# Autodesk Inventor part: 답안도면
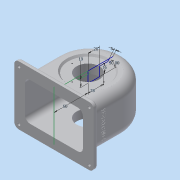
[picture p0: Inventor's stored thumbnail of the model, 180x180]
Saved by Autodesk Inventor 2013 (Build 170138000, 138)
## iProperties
Created: 2016-01
Part Number: 답안도면
Material: 일반
Document SubType Name: Modeling
Designer: Administrator
Density: 1 g/cm^3
Author: Administrator
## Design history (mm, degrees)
sketch "스케치1"
  geometry: L1 (-51, 0)-(-51, -64); L2 (51, 0)-(51, -64); L3 (-57, -64)-(-57, 0); L4 (57, 0)-(57, -64); L5 (-57, -64)-(-51, -64); L6 (51, -64)-(57, -64); A1 r 51 centre (0, 0) between (51, 0) and (-51, 0); A2 r 57 centre (0, 0) between (57, 0) and (-57, 0); 1 further point
  constraints: 12 end point, 4 point on circle, 2 centre point, 2 parallel, 2 perpendicular, 2 tangent, 1 coincident, 1 collinear, 1 vertical
  dimensions: "d0" = 102 diameter of A1; "d2" = 6 distance between parallel lines of L3 L1; "d4" = 6 radial gap between concentric circles of A1 A2; "d6" = 64 vertical distance of L4.end point (0, 0); "d7" = 6 distance between parallel lines of L2 L4
extrude "돌출1" new body sketch "스케치1" stored distance "d8" = 77; taper "d9" = 0 deg
sketch "스케치2"
  geometry: L1 (-51, -64)-(-51, 0) reference; L2 (51, 0)-(51, -64) reference; L3 (-51, -64)-(-46.848, -64); L4 (-46.848, -64)-(51, -64); A1 r 51 centre (0, 0) between (51, 0) and (-51, 0) reference; 1 further point
  constraints: 4 end point, 1 collinear
extrude "돌출2" join sketch "스케치2" distance "d10" = 5; taper "d11" = 0 deg
sketch "스케치3"
  geometry: L1 (51, 0)-(51, -64) reference; L2 (51, -64)-(57, -64) reference; L3 (57, -64)-(57, 0) reference; L4 (-57, 0)-(-57, -64) reference; L5 (-57, -64)-(-51, -64) reference; L6 (-51, -64)-(-51, 0) reference; L7 (-51, -64)-(51, -64); A1 r 51 centre (0, 0) between (51, 0) and (-51, 0) reference; A2 r 57 centre (0, 0) between (57, 0) and (-57, 0) reference; 1 further point
  constraints: 2 end point, 1 perpendicular
extrude "돌출3" join sketch "스케치3" distance "d12" = 5; taper "d13" = 0 deg
sketch "스케치5"
  geometry: L1 (-57, -64)-(57, -64) reference; C1 r 31 at (0, -4); A1 r 57 centre (0, 0) between (57, 0) and (-57, 0) reference; 1 further point
  constraints: 1 centre point, 1 vertical alignment
  dimensions: "d89" = 62 diameter of C1; "d91" = 60 distance from line of L1 C1.centre
extrude "돌출4" join sketch "스케치5" distance "d25" = 10; taper "d26" = 0 deg
sketch "스케치6"
  geometry: L1 (127, 90.5)-(-13, 90.5); L2 (-13, 90.5)-(-13, -13.5); L3 (-13, -13.5)-(127, -13.5); L4 (127, -13.5)-(127, 90.5); L5 (0, 77)-(114, 77) reference; L6 (114, 0)-(114, 77) reference; L7 (114, 0)-(0, 0) reference; L8 (0, 0)-(0, 77) reference; 1 further point
  constraints: 8 end point, 2 parallel, 1 horizontal, 1 perpendicular
  dimensions: "d27" = 140 distance of L2.end L3.end; "d29" = 104 distance of L3.end L1.start; "d30" = 70 distance from line of point (57, 38.5) L4; "d31" = 52 distance from line of L1 point (57, 38.5)
fillet "모깎기1" dims "d34" = 9
extrude "돌출7" join sketch "스케치6" distance "d48" = 7; taper "d49" = 0 deg
fillet "모깎기4" dims "d50" = 17
fillet "모깎기5" dims "d73" = 8
fillet "모깎기6" dims "d74" = 3
sketch "스케치11"
  geometry: L1 (124, 104)-(0, 104) reference; L2 (-8, 96)-(-8, 8) reference; L3 (0, 0)-(124, 0) reference; L4 (132, 8)-(132, 96) reference; C1 r 2.5 at (0, 96); C2 r 2.5 at (0, 8); C3 r 2.5 at (124, 8); C4 r 2.5 at (124, 96); A1 r 8 centre (0, 96) between (0, 104) and (-8, 96) reference; A2 r 8 centre (0, 8) between (-8, 8) and (0, 0) reference; A3 r 8 centre (124, 8) between (124, 0) and (132, 8) reference; A4 r 8 centre (124, 96) between (132, 96) and (124, 104) reference; 1 further point
  constraints: 4 centre point, 4 coincident
  dimensions: "d75" = 5 diameter of C1; "d77" = 5 diameter of C4; "d78" = 5 diameter of C3; "d79" = 5 diameter of C2
sketch "스케치12"
  geometry: L1 (-57, 38.5)-(0, 38.5) reference; L2 (0, 33.5)-(-64, 33.5) reference; L3 (-64, -44)-(-64, 44) reference; L4 (-4, 38.5)-(-4, 19.5); L5 (-4, 19.5)-(24, 19.5); L6 (24, 19.5)-(39.943, 38.5); L7 (0, 38.5)-(40, 38.5) reference; L8 (16, 19.5)-(16, 35.5); L9 (16, 35.5)-(30.899, 35.5); L10 (30.899, 35.5)-(33.416, 38.5); L11 (39.943, 38.5)-(33.416, 38.5); L12 (33.416, 38.5)-(-4, 38.5); 1 further point
  constraints: 16 end point, 4 point on line, 3 parallel, 3 perpendicular
  dimensions: "d80" = 19 distance between parallel lines of L1 L5; "d81" = 50 deg angle of L5 L6; "d82" = 5 distance between parallel lines of L10 L6; "d83" = 60 distance between parallel lines of L3 L4; "d84" = 28 distance from line of L4 L5.end; "d85" = 16 distance of L8.start L8.end; "d86" = 20 distance between parallel lines of L4 L8
revolve "회전3" stored, may be unused: angle "d87" = 90 deg
revolve "회전4" stored, may be unused: angle "d88" = 90 deg
sketch "스케치13"
  geometry: C1 r 31 at (0, 0) reference; A1 r 24 centre (0, 0) between (0, 24) and (0, -24); 5 further points
  constraints: 4 point on circle, 3 coincident, 2 horizontal alignment, 2 vertical alignment, 1 centre point
  dimensions: "d92" = 48 diameter of A1
hole "구멍4" sketch "스케치13" at (-24, 0), (0, 24), (0, -24), (24, 0) diameter "d94" = 2.459; stored, may be unused: countersink angle "d98" = 90 deg, drill point angle "d100" = 118 deg; dims "d95" = 6, "d96" = 4, "d97" = 2, "d99" = 8
sketch "스케치14"
  geometry: C1 r 34.899 at (0, 0) reference; C2 r 20 at (0, 0) reference; A1 r 28 centre (0, 0) between (0, 28) and (-28, 0); 3 further points
  constraints: 4 point on circle, 2 horizontal alignment, 1 centre point, 1 coincident, 1 vertical alignment
  dimensions: "d101" = 56 diameter of A1
hole "구멍5" sketch "스케치14" at (0, 28), (28, 0), (0, -28), (-28, 0) diameter "d103" = 2.459; stored, may be unused: countersink angle "d107" = 90 deg, drill point angle "d109" = 118 deg; dims "d104" = 7, "d105" = 4, "d106" = 2, "d108" = 9
hole "구멍6" diameter "d112" = 40; stored, may be unused: countersink angle "d116" = 90 deg, drill point angle "d118" = 0 deg; dims "d113" = 40, "d114" = 4, "d115" = 2, "d117" = 20, "d144" = 10, "d145" = 10
node "작업 평면1"
sketch "스케치15"
  geometry: C1 r 6 at (62, 52); 1 further point
  constraints: 1 centre point, 1 coincident
  dimensions: "d120" = 12 diameter of C1
extrude "돌출8" join sketch "스케치15" distance "d122" = 7; taper "d123" = 0 deg
hole "구멍7" diameter "d126" = 4.459; stored, may be unused: countersink angle "d130" = 90 deg, drill point angle "d132" = 0 deg; dims "d124" = 10, "d125" = 10, "d127" = 15, "d128" = 4, "d129" = 2, "d131" = 15
sketch "스케치16"
  geometry: L1 (-17, 34.807)-(-17, 0) reference; L2 (65.5, -7)-(-22.5, -7) reference; 2 further points
  constraints: 1 other
  dimensions: "d133" = 38.5 distance from line of L1 point (21.5, 23); "d134" = 30 distance from line of L2 point (21.5, 23)
feature "엠보싱1" sketch "스케치16" dims "d0" = 102, "d2" = 6, "d4" = 6, "d6" = 64, "d7" = 6, "d135" = 0.5, "d136" = 0
fillet "모깎기7" dims "d137" = 3
fillet "모깎기8" dims "d138" = 3
fillet "모깎기9" dims "d139" = 1
extrude "돌출10" cut sketch "스케치11" distance "d142" = 7; taper "d143" = 0 deg
node "솔리드1"
node "투영된 루프1"
node "투영된 루프3"
other parameters: "d3" = 64, "d20" = 62, "d119" = -127
